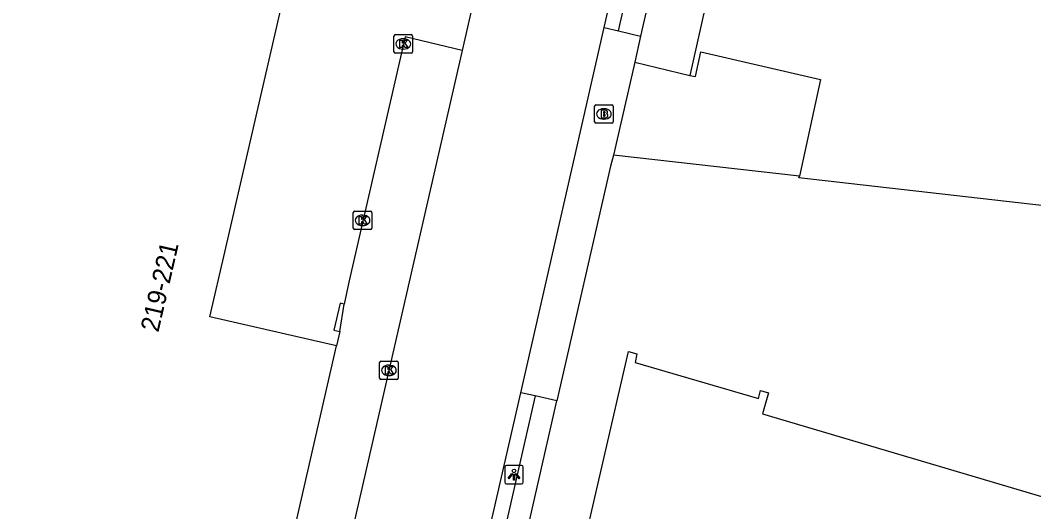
# Model space of a CAD drawing. Extents: x 161389 to 162585, y 388479 to 389761.
# Drawn here: x 162340.8 to 162395.4, y 388892.5 to 388919 of the extents above; entities that cross this region are included whole.
import ezdxf

# ---------------------------------------------------------------- set-up
doc = ezdxf.new("R2010")
doc.units = 0
for name, color, linetype in [('IMGEO_Brandkraan', 7, 'Continuous'), ('IMGEO_Groenvoorziening', 7, 'Continuous'), ('IMGEO_Kolk', 7, 'Continuous'), ('IMGEO_Lichtpunt', 7, 'Continuous'), ('IMGEO_Pand', 7, 'Continuous'), ('IMGEO_Pand_nummerreeks', 7, 'Continuous'), ('IMGEO_Parkeervlak_open', 7, 'Continuous'), ('IMGEO_Rijbaan_lokaal_gesloten', 7, 'Continuous'), ('IMGEO_Voetpad_open', 7, 'Continuous')]:
    doc.layers.add(name, color=color, linetype=linetype)

msp = doc.modelspace()

# ---------------------------------------------------------------- linework, layer by layer
at = {"layer": 'IMGEO_Brandkraan'}
for p, q in [((162371.749, 388913.491), (162371.749, 388914.343)), ((162371.824, 388914.417), (162372.676, 388914.417)), ((162372.75, 388914.343), (162372.75, 388913.491)), ((162372.237, 388914.197), (162372.262, 388914.197)), ((162372.676, 388913.417), (162371.824, 388913.417)), ((162372.26, 388913.637), (162372.235, 388913.637))]:
    msp.add_line(p, q, dxfattribs=at)
for points in [[(162371.749, 388913.491), (162371.749, 388914.343)], [(162371.824, 388914.417), (162372.676, 388914.417)], [(162372.75, 388914.343), (162372.75, 388913.491)], [(162372.097, 388914.117), (162372.097, 388913.717), (162372.31, 388913.717)], [(162372.328, 388914.117), (162372.097, 388914.117)], [(162372.276, 388914.036), (162372.222, 388914.036), (162372.222, 388913.96)], [(162372.222, 388913.96), (162372.275, 388913.96)], [(162372.284, 388913.884), (162372.222, 388913.884), (162372.222, 388913.803)], [(162372.222, 388913.803), (162372.284, 388913.803)], [(162372.676, 388913.417), (162371.824, 388913.417)]]:
    msp.add_lwpolyline(points, dxfattribs=at)
for centre, radius, start, end in [((162371.826, 388914.341), 0.0765, 91.552, 178.448), ((162371.826, 388914.341), 0.0765, 91.552, 178.448), ((162372.674, 388914.341), 0.0765, 1.552, 88.448), ((162372.674, 388914.341), 0.0765, 1.552, 88.448), ((162372.277, 388913.998), 0.0379, 267.8285, 90.9355), ((162372.285, 388913.843), 0.0404, 269.8759, 90.5077), ((162372.316, 388913.968), 0.251, 268.6676, 293.5347), ((162372.332, 388913.972), 0.145, 59.4692, 91.5367), ((162372.357, 388914.019), 0.0922, 285.5137, 58.1501), ((162372.362, 388913.827), 0.105, 301.3115, 78.989), ((162371.826, 388913.493), 0.0765, 181.552, 268.448), ((162371.826, 388913.493), 0.0765, 181.552, 268.448), ((162372.674, 388913.493), 0.0765, 271.552, 358.448), ((162372.674, 388913.493), 0.0765, 271.552, 358.448)]:
    msp.add_arc(centre, radius, start, end, dxfattribs=at)
for centre, major_axis, ratio, start_param, end_param in [((162372.236, 388913.917), (-0.387, 0.002), 0.722429, 4.712389, 7.853982), ((162372.261, 388913.917), (-0.39, 0.002), 0.717154, 1.570796, 4.712389)]:
    msp.add_ellipse(centre, major_axis=major_axis, ratio=ratio, start_param=start_param, end_param=end_param, dxfattribs=at)
at = {"layer": 'IMGEO_Groenvoorziening'}
for points in [[(162364.598, 388917.339), (162361.52, 388918.083), (162358.494, 388904.839), (162358.235, 388903.661)], [(162357.992, 388902.187), (162357.822, 388901.413)]]:
    msp.add_lwpolyline(points, dxfattribs=at)
at = {"layer": 'IMGEO_Kolk'}
for p, q in [((162360.922, 388917.268), (162360.922, 388918.12)), ((162360.997, 388918.194), (162361.849, 388918.194)), ((162361.923, 388918.12), (162361.923, 388917.268)), ((162361.41, 388917.974), (162361.435, 388917.974)), ((162361.849, 388917.194), (162360.997, 388917.194)), ((162361.433, 388917.414), (162361.408, 388917.414)), ((162358.725, 388907.754), (162358.725, 388908.606)), ((162358.8, 388908.68), (162359.652, 388908.68)), ((162359.213, 388908.46), (162359.238, 388908.46)), ((162359.726, 388908.606), (162359.726, 388907.754)), ((162359.652, 388907.68), (162358.8, 388907.68)), ((162359.236, 388907.9), (162359.211, 388907.9)), ((162360.221, 388900.591), (162361.073, 388900.591)), ((162360.146, 388899.665), (162360.146, 388900.517)), ((162360.634, 388900.371), (162360.659, 388900.371)), ((162361.147, 388900.517), (162361.147, 388899.665)), ((162361.073, 388899.591), (162360.221, 388899.591)), ((162360.657, 388899.811), (162360.632, 388899.811))]:
    msp.add_line(p, q, dxfattribs=at)
for points in [[(162360.922, 388917.268), (162360.922, 388918.12)], [(162360.997, 388918.194), (162361.849, 388918.194)], [(162361.923, 388918.12), (162361.923, 388917.268)], [(162361.243, 388917.894), (162361.366, 388917.894), (162361.366, 388917.743), (162361.496, 388917.894), (162361.66, 388917.894), (162361.514, 388917.743), (162361.667, 388917.494), (162361.515, 388917.494), (162361.43, 388917.658), (162361.366, 388917.591), (162361.366, 388917.494), (162361.243, 388917.494), (162361.243, 388917.894)], [(162361.849, 388917.194), (162360.997, 388917.194)], [(162358.725, 388907.754), (162358.725, 388908.606)], [(162358.8, 388908.68), (162359.652, 388908.68)], [(162359.046, 388908.38), (162359.169, 388908.38), (162359.169, 388908.229), (162359.299, 388908.38), (162359.463, 388908.38), (162359.317, 388908.229), (162359.47, 388907.98), (162359.318, 388907.98), (162359.233, 388908.144), (162359.169, 388908.077), (162359.169, 388907.98), (162359.046, 388907.98), (162359.046, 388908.38)], [(162359.726, 388908.606), (162359.726, 388907.754)], [(162359.652, 388907.68), (162358.8, 388907.68)], [(162360.221, 388900.591), (162361.073, 388900.591)], [(162360.146, 388899.665), (162360.146, 388900.517)], [(162360.467, 388900.291), (162360.59, 388900.291), (162360.59, 388900.14), (162360.72, 388900.291), (162360.884, 388900.291), (162360.738, 388900.14), (162360.891, 388899.891), (162360.739, 388899.891), (162360.654, 388900.055), (162360.59, 388899.988), (162360.59, 388899.891), (162360.467, 388899.891), (162360.467, 388900.291)], [(162361.147, 388900.517), (162361.147, 388899.665)], [(162361.073, 388899.591), (162360.221, 388899.591)]]:
    msp.add_lwpolyline(points, dxfattribs=at)
for centre, start, end in [((162360.999, 388918.118), 91.552, 178.448), ((162360.999, 388918.118), 91.552, 178.448), ((162361.847, 388918.118), 1.552, 88.448), ((162361.847, 388918.118), 1.552, 88.448), ((162360.999, 388917.27), 181.552, 268.448), ((162360.999, 388917.27), 181.552, 268.448), ((162361.847, 388917.27), 271.552, 358.448), ((162361.847, 388917.27), 271.552, 358.448), ((162358.802, 388908.604), 91.552, 178.448), ((162358.802, 388908.604), 91.552, 178.448), ((162359.65, 388908.604), 1.552, 88.448), ((162359.65, 388908.604), 1.552, 88.448), ((162358.802, 388907.756), 181.552, 268.448), ((162358.802, 388907.756), 181.552, 268.448), ((162359.65, 388907.756), 271.552, 358.448), ((162359.65, 388907.756), 271.552, 358.448), ((162360.223, 388900.515), 91.552, 178.448), ((162360.223, 388900.515), 91.552, 178.448), ((162361.071, 388900.515), 1.552, 88.448), ((162361.071, 388900.515), 1.552, 88.448), ((162360.223, 388899.667), 181.552, 268.448), ((162360.223, 388899.667), 181.552, 268.448), ((162361.071, 388899.667), 271.552, 358.448), ((162361.071, 388899.667), 271.552, 358.448)]:
    msp.add_arc(centre, 0.0765, start, end, dxfattribs=at)
for centre, major_axis, ratio, start_param, end_param in [((162361.409, 388917.694), (-0.387, 0.002), 0.722429, 4.712389, 7.853982), ((162361.434, 388917.694), (-0.39, 0.002), 0.717154, 1.570796, 4.712389), ((162359.212, 388908.18), (-0.387, 0.002), 0.722429, 4.712389, 7.853982), ((162359.237, 388908.18), (-0.39, 0.002), 0.717154, 1.570796, 4.712389), ((162360.633, 388900.091), (-0.387, 0.002), 0.722429, 4.712389, 7.853982), ((162360.658, 388900.091), (-0.39, 0.002), 0.717154, 1.570796, 4.712389)]:
    msp.add_ellipse(centre, major_axis=major_axis, ratio=ratio, start_param=start_param, end_param=end_param, dxfattribs=at)
at = {"layer": 'IMGEO_Lichtpunt'}
for p, q in [((162366.9, 388894.87), (162366.9, 388894.063)), ((162366.9, 388894.87), (162366.9, 388894.063)), ((162367.802, 388894.965), (162366.994, 388894.965)), ((162367.802, 388894.965), (162366.994, 388894.965)), ((162367.896, 388894.063), (162367.896, 388894.87)), ((162367.896, 388894.063), (162367.896, 388894.87)), ((162366.994, 388893.969), (162367.802, 388893.969)), ((162366.994, 388893.969), (162367.802, 388893.969))]:
    msp.add_line(p, q, dxfattribs=at)
for points in [[(162367.274, 388894.534), (162367.313, 388894.506), (162367.125, 388894.244), (162367.087, 388894.271), (162367.274, 388894.534)], [(162367.486, 388894.506), (162367.524, 388894.533), (162367.711, 388894.271), (162367.672, 388894.243), (162367.486, 388894.506)], [(162367.376, 388894.486), (162367.423, 388894.486), (162367.423, 388894.164), (162367.376, 388894.164), (162367.376, 388894.486)]]:
    msp.add_lwpolyline(points, dxfattribs=at)
msp.add_circle((162367.399, 388894.668), 0.0994, dxfattribs=at)
for centre, start, end in [((162366.994, 388894.87), 90, 180), ((162366.994, 388894.87), 90, 180), ((162367.802, 388894.87), 0, 90), ((162367.802, 388894.87), 0, 90), ((162366.994, 388894.063), 180, 270), ((162366.994, 388894.063), 180, 270), ((162367.802, 388894.063), 270, 0), ((162367.802, 388894.063), 270, 360)]:
    msp.add_arc(centre, 0.0946, start, end, dxfattribs=at)
at = {"layer": 'IMGEO_Pand'}
for points in [[(162357.822, 388901.413), (162350.993, 388902.975), (162351.799, 388906.466), (162359.012, 388937.762), (162358.244, 388937.938), (162354.138, 388938.878), (162348.019, 388940.254), (162347.32, 388937.213), (162321.535, 388943.142), (162322.217, 388946.171), (162311.401, 388948.624), (162301.281, 388884.015), (162300.445, 388878.969)], [(162377.723, 388919.68), (162376.89, 388915.999)], [(162376.89, 388915.999), (162377.186, 388915.933), (162377.481, 388917.261), (162383.947, 388915.774), (162382.804, 388910.563)], [(162431.867, 388904.877), (162382.772, 388910.464), (162382.804, 388910.563)], [(162358.235, 388903.661), (162358.012, 388903.711), (162357.684, 388902.256), (162357.992, 388902.187)], [(162357.992, 388902.187), (162358.235, 388903.661)], [(162329.062, 388883.383), (162335.09, 388882.809), (162334.421, 388875.837), (162348.394, 388874.517), (162351.606, 388874.213), (162351.615, 388874.313), (162352.295, 388877.281), (162357.822, 388901.413)], [(162391.857, 388867.872), (162392.177, 388870.683), (162368.656, 388877.64), (162368.47, 388876.966), (162368.037, 388877.085), (162373.582, 388901.101), (162374.02, 388900.974), (162373.932, 388900.514), (162380.594, 388898.564), (162380.7, 388899.012), (162381.135, 388898.887), (162380.807, 388897.743), (162396.969, 388892.972), (162430.252, 388889.19), (162427.372, 388863.825)]]:
    msp.add_lwpolyline(points, dxfattribs=at)
at = {"layer": 'IMGEO_Parkeervlak_open'}
for points in [[(162373.918, 388916.715), (162376.89, 388915.999)], [(162382.804, 388910.563), (162372.768, 388911.699)]]:
    msp.add_lwpolyline(points, dxfattribs=at)
at = {"layer": 'IMGEO_Rijbaan_lokaal_gesloten'}
for points in [[(162372.264, 388918.571), (162375.111, 388931.012)], [(162365.886, 388922.955), (162364.598, 388917.339)], [(162367.76, 388898.886), (162370.658, 388911.551), (162372.264, 388918.571)], [(162364.598, 388917.339), (162355.936, 388879.524), (162354.085, 388871.528)], [(162361.659, 388872.226), (162367.76, 388898.886)]]:
    msp.add_lwpolyline(points, dxfattribs=at)
at = {"layer": 'IMGEO_Voetpad_open'}
for points in [[(162373.047, 388918.403), (162375.876, 388930.85)], [(162377.087, 388930.6), (162374.231, 388918.115)], [(162372.264, 388918.571), (162373.047, 388918.403)], [(162373.047, 388918.403), (162374.231, 388918.115)], [(162374.231, 388918.115), (162373.918, 388916.715)], [(162373.918, 388916.715), (162372.768, 388911.699)], [(162372.768, 388911.699), (162372.602, 388911.097), (162369.717, 388898.438)], [(162368.533, 388898.709), (162367.76, 388898.886)], [(162368.533, 388898.709), (162362.453, 388872.044), (162361.659, 388872.226)], [(162364.588, 388875.934), (162369.717, 388898.438)], [(162369.717, 388898.438), (162368.533, 388898.709)]]:
    msp.add_lwpolyline(points, dxfattribs=at)

# ---------------------------------------------------------------- texts
at = {"layer": 'IMGEO_Pand_nummerreeks'}
msp.add_text('219-221', height=1, rotation=76.9994, dxfattribs=at).set_placement((162348.206, 388902.106))

doc.saveas('drawing.dxf')
